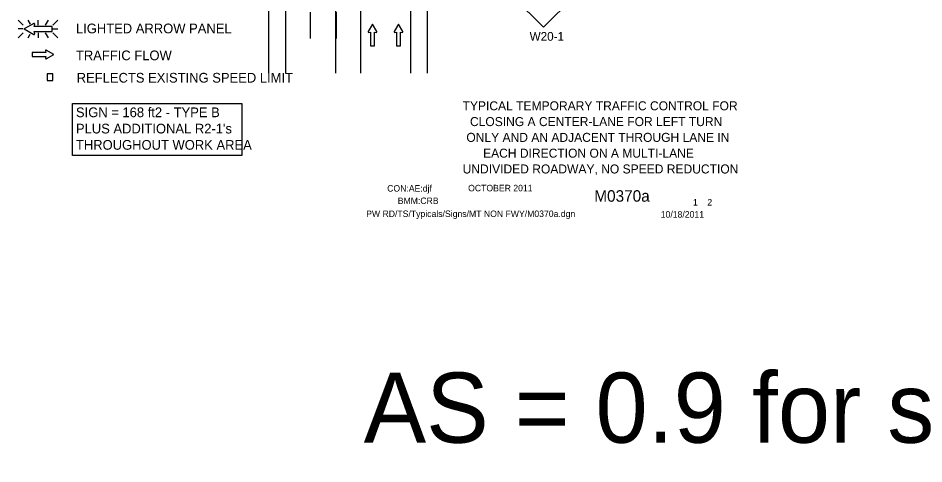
# Model space of a CAD drawing. Extents: x 16735 to 18475, y 6983 to 8262.
# Drawn here: x 16737 to 17605, y 6983 to 7411 of the extents above; entities that cross this region are included whole.
import ezdxf

# ---------------------------------------------------------------- set-up
doc = ezdxf.new("R2010")
doc.units = 0
for name, color, linetype in [('BORDER_SIGNAL_WO', 7, 'Continuous'), ('MT_SCRATCH_LEVEL_E', 7, 'Continuous'), ('PAVT_EDGE_EX', 7, 'Continuous'), ('TRAFFIC_SIGNS_PR', 7, 'Continuous'), ('TYPICAL_TEXT_DIMEN_EX', 7, 'Continuous'), ('TYPICAL_TEXT_DIMEN_PR', 7, 'Continuous')]:
    doc.layers.add(name, color=color, linetype=linetype)

msp = doc.modelspace()

# ---------------------------------------------------------------- linework, layer by layer
at = {"layer": 'MT_SCRATCH_LEVEL_E'}
for p, q in [((17076.52, 7404.83), (17072.41, 7397.59)), ((17076.52, 7404.83), (17072.41, 7397.59)), ((17080.67, 7397.59), (17076.52, 7404.83)), ((17080.67, 7397.59), (17076.52, 7404.83)), ((17101.61, 7404.83), (17097.5, 7397.59)), ((17101.61, 7404.83), (17097.5, 7397.59)), ((17105.75, 7397.59), (17101.61, 7404.83)), ((17105.75, 7397.59), (17101.61, 7404.83)), ((17072.89, 7396.91), (17074.67, 7397.22)), ((17072.89, 7396.91), (17074.67, 7397.22)), ((17074.67, 7397.22), (17074.67, 7383.97)), ((17074.67, 7397.22), (17074.67, 7383.97)), ((17078.41, 7383.97), (17078.41, 7397.22)), ((17078.41, 7397.22), (17080.19, 7396.91)), ((17078.41, 7383.97), (17078.41, 7397.22)), ((17078.41, 7397.22), (17080.19, 7396.91)), ((17097.98, 7396.91), (17099.76, 7397.22)), ((17097.98, 7396.91), (17099.76, 7397.22)), ((17099.76, 7397.22), (17099.76, 7383.97)), ((17099.76, 7397.22), (17099.76, 7383.97)), ((17103.5, 7383.97), (17103.5, 7397.22)), ((17103.5, 7397.22), (17105.28, 7396.91)), ((17103.5, 7383.97), (17103.5, 7397.22)), ((17103.5, 7397.22), (17105.28, 7396.91)), ((17074.67, 7383.97), (17078.41, 7383.97)), ((17074.67, 7383.97), (17078.41, 7383.97)), ((17099.76, 7383.97), (17103.5, 7383.97)), ((17099.76, 7383.97), (17103.5, 7383.97)), ((16763.5, 7377.67), (16750.24, 7377.67)), ((16750.24, 7377.67), (16750.24, 7373.92)), ((16763.5, 7377.67), (16750.24, 7377.67)), ((16750.24, 7377.67), (16750.24, 7373.92)), ((16750.24, 7373.92), (16763.5, 7373.92)), ((16750.24, 7373.92), (16763.5, 7373.92)), ((16763.19, 7379.44), (16763.5, 7377.67)), ((16763.19, 7379.44), (16763.5, 7377.67)), ((16763.5, 7373.92), (16763.19, 7372.15)), ((16763.5, 7373.92), (16763.19, 7372.15)), ((16771.11, 7375.81), (16763.87, 7379.92)), ((16771.11, 7375.81), (16763.87, 7379.92)), ((16763.87, 7371.67), (16771.11, 7375.81)), ((16763.87, 7371.67), (16771.11, 7375.81))]:
    msp.add_line(p, q, dxfattribs=at)
for centre, start, end in [((17072.81, 7397.37), 150.42484, 279.96381), ((17072.81, 7397.37), 150.42484, 279.96381), ((17080.26, 7397.37), 260.03619, 29.77312), ((17080.26, 7397.37), 260.03619, 29.77312), ((17097.9, 7397.37), 150.42484, 279.96381), ((17097.9, 7397.37), 150.42484, 279.96381), ((17105.34, 7397.37), 260.03619, 29.77312), ((17105.34, 7397.37), 260.03619, 29.77312), ((16763.65, 7379.52), 60.42484, 189.96381), ((16763.65, 7379.52), 60.42484, 189.96381), ((16763.65, 7372.08), 170.03619, 299.77312), ((16763.65, 7372.08), 170.03619, 299.77312)]:
    msp.add_arc(centre, 0.463, start, end, dxfattribs=at)
at = {"layer": 'PAVT_EDGE_EX'}
for p, q in [((16977.08, 8195.21), (16977.08, 7357.91)), ((16993.08, 8195.21), (16993.08, 7357.91)), ((17041.08, 8195.21), (17041.08, 7357.91)), ((17065.08, 8195.21), (17065.08, 7357.91)), ((17113.08, 8195.21), (17113.08, 7357.91)), ((17129.08, 8195.21), (17129.08, 7357.91))]:
    msp.add_line(p, q, dxfattribs=at)
for points in [[(17017.08, 7391.16), (17017.08, 7416.16)], [(17042.08, 7391.16), (17042.08, 7416.16)]]:
    msp.add_lwpolyline(points, dxfattribs=at)
at = {"layer": 'TRAFFIC_SIGNS_PR'}
for p, q in [((17210.03, 7432.26), (17240.57, 7401.72)), ((17240.57, 7401.72), (17271.12, 7432.26)), ((16736.9, 7408.6), (16741.84, 7403.67)), ((16748.67, 7404.78), (16746.46, 7408.61)), ((16755.99, 7403.67), (16755.99, 7408.61)), ((16763.22, 7403.67), (16766.07, 7408.61)), ((16770.13, 7403.67), (16775.07, 7408.61)), ((16741.84, 7400.12), (16736.9, 7400.12)), ((16770.13, 7400.12), (16775.07, 7400.12)), ((16736.9, 7391.63), (16741.84, 7396.56)), ((16746.41, 7391.63), (16748.53, 7395.29)), ((16755.99, 7396.56), (16755.99, 7391.63)), ((16766.11, 7391.63), (16763.27, 7396.56)), ((16770.13, 7396.56), (16775.07, 7391.62))]:
    msp.add_line(p, q, dxfattribs=at)
for points in [[(16751.91, 7405.39), (16742.62, 7400.12), (16751.92, 7394.8)], [(16752.79, 7395.42), (16752.39, 7397.69), (16769.4, 7397.69), (16769.4, 7402.49), (16752.39, 7402.49), (16752.79, 7404.77)]]:
    msp.add_lwpolyline(points, dxfattribs=at)
msp.add_lwpolyline([(16764.71, 7350.91), (16770.3, 7350.91), (16770.3, 7357.08), (16764.71, 7357.08)], close=True, dxfattribs=at)
for centre, radius, start, end in [((16752.2, 7404.87), 0.598, 350.73078, 118.89165), ((16752.2, 7395.32), 0.597, 241.48329, 9.95933)]:
    msp.add_arc(centre, radius, start, end, dxfattribs=at)
at = {"layer": 'TYPICAL_TEXT_DIMEN_EX'}
msp.add_lwpolyline([(16788.98, 7328.73), (16951.46, 7328.73), (16951.46, 7278.92), (16788.98, 7278.92)], close=True, dxfattribs=at)

# ---------------------------------------------------------------- texts
at = {"layer": 'BORDER_SIGNAL_WO'}
for s, height, p in [('TYPICAL TEMPORARY TRAFFIC CONTROL FOR', 8.6352, (17162.96, 7322.21)), ('CLOSING A CENTER-LANE FOR LEFT TURN', 8.6352, (17170.05, 7307.07)), ('ONLY AND AN ADJACENT THROUGH LANE IN', 8.6352, (17166.6, 7291.94)), ('EACH DIRECTION ON A MULTI-LANE ', 8.6352, (17182.6, 7276.81)), ('UNDIVIDED ROADWAY, NO SPEED REDUCTION', 8.6352, (17163.02, 7261.67)), ('CON:AE:djf', 6.2, (17090.69, 7244.31)), ('    OCTOBER 2011    ', 6.2, (17159.08, 7244.59)), ('    M0370a   ', 11, (17272.86, 7234.63)), ('BMM:CRB   ', 6.2, (17100.81, 7232.42)), (' 1    2 ', 6.2, (17381.45, 7230.95)), ('PW RD/TS/Typicals/Signs/MT NON FWY/M0370a.dgn     ', 6.2, (17070.55, 7219.96)), ('10/18/2011    ', 6.2, (17352.93, 7219.38))]:
    msp.add_text(s, height=height, dxfattribs=at).set_placement(p)
at = {"layer": 'TRAFFIC_SIGNS_PR'}
msp.add_text('W20-1', height=8.37, dxfattribs=at).set_placement((17227.26, 7388.85))
at = {"layer": 'TYPICAL_TEXT_DIMEN_EX'}
for s, p in [('LIGHTED ARROW PANEL', (16792.33, 7395.98)), ('TRAFFIC FLOW', (16792.33, 7370.18)), ('REFLECTS EXISTING SPEED LIMIT', (16793.08, 7348.76)), ('SIGN = 168 ft2 - TYPE B', (16792.33, 7315.62)), ("PLUS ADDITIONAL R2-1's", (16792.33, 7300.02)), ('THROUGHOUT WORK AREA', (16792.33, 7284.42))]:
    msp.add_text(s, height=9.3, dxfattribs=at).set_placement(p)
at = {"layer": 'TYPICAL_TEXT_DIMEN_PR'}
msp.add_text('AS = 0.9 for signs', height=67.2, dxfattribs=at).set_placement((17068.13, 7003.66))

doc.saveas('drawing.dxf')
